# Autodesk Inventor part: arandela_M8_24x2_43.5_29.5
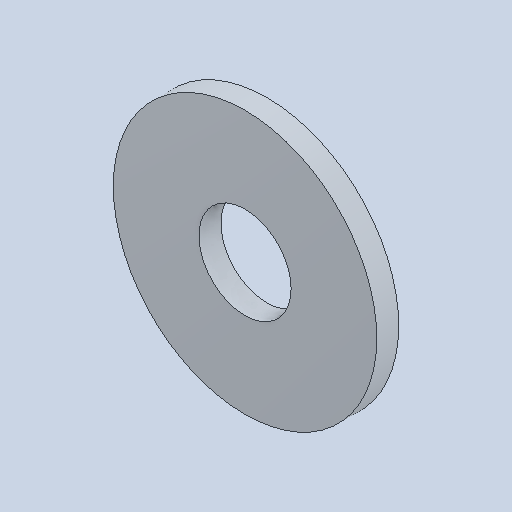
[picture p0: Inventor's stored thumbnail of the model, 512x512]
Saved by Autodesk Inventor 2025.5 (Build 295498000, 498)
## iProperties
Created: 2026-10
Part Number: arandela_M8_24x2_43.5_29.5
Material: Genérico
Document SubType Name: Modeling
Designer: Luis M
Density: 1 g/cm^3
Appearance: Valor por defecto
Author: Luis M
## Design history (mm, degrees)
feature "Base1"
node "Sólido1"
